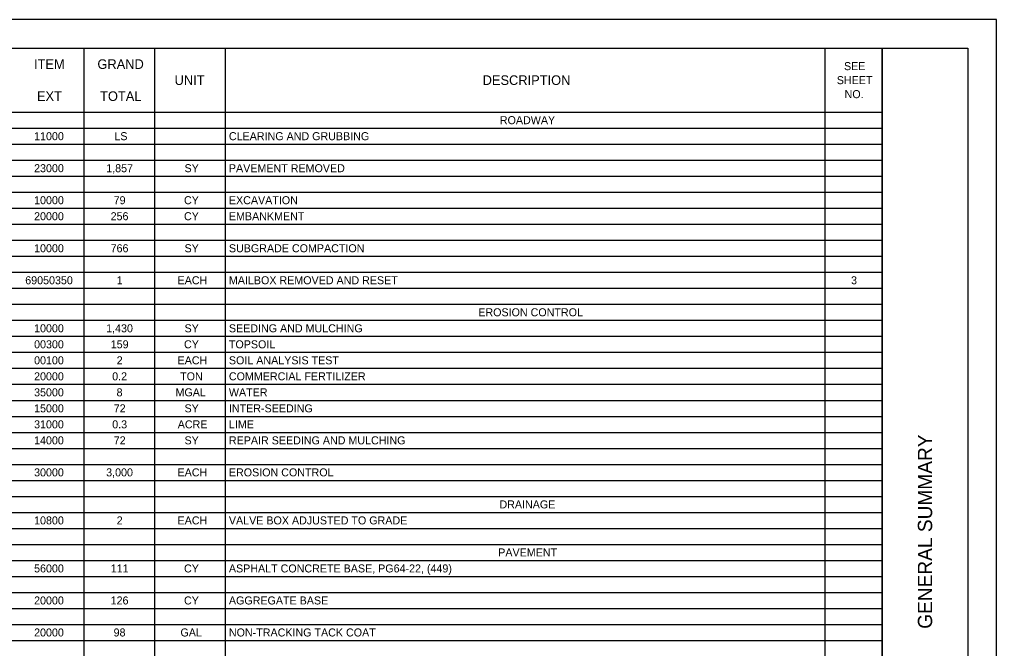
# Model space of a CAD drawing. Extents: x 0 to 34, y 0 to 22.
# Drawn here: x 16.91 to 34, y 11 to 22 of the extents above; entities that cross this region are included whole.
import ezdxf

# ---------------------------------------------------------------- set-up
doc = ezdxf.new("R2010")
doc.units = 0
for name, color, linetype in [('Default', 7, 'Continuous'), ('SH_Border', 7, 'Continuous'), ('SH_Cut_Line', 7, 'Continuous'), ('SH_Data', 7, 'Continuous')]:
    doc.layers.add(name, color=color, linetype=linetype)

msp = doc.modelspace()

# ---------------------------------------------------------------- linework, layer by layer
at = {"layer": 'Default'}
for p, q in [((1.5, 21.5), (32.002, 21.5)), ((18.036, 21.5), (18.036, 0.501)), ((19.271, 21.5), (19.271, 0.501)), ((20.506, 21.5), (20.506, 0.501)), ((30.998, 21.5), (30.998, 0.501)), ((32.002, 21.5), (32.002, 0.501)), ((1.5, 20.38), (32.002, 20.38)), ((1.5, 20.1), (32.002, 20.1)), ((1.5, 19.82), (32.002, 19.82)), ((1.5, 19.54), (32.002, 19.54)), ((1.5, 19.26), (32.002, 19.26)), ((1.5, 18.98), (32.002, 18.98)), ((1.5, 18.7), (32.002, 18.7)), ((1.5, 18.42), (32.002, 18.42)), ((1.5, 18.14), (32.002, 18.14)), ((1.5, 17.86), (32.002, 17.86)), ((1.5, 17.58), (32.002, 17.58)), ((1.5, 17.3), (32.002, 17.3)), ((1.5, 17.02), (32.002, 17.02)), ((1.5, 16.74), (32.002, 16.74)), ((1.5, 16.46), (32.002, 16.46)), ((1.5, 16.18), (32.002, 16.18)), ((1.5, 15.9), (32.002, 15.9)), ((1.5, 15.62), (32.002, 15.62)), ((1.5, 15.34), (32.002, 15.34)), ((1.5, 15.06), (32.002, 15.06)), ((1.5, 14.78), (32.002, 14.78)), ((1.5, 14.5), (32.002, 14.5)), ((1.5, 14.22), (32.002, 14.22)), ((1.5, 13.94), (32.002, 13.94)), ((1.5, 13.66), (32.002, 13.66)), ((1.5, 13.38), (32.002, 13.38)), ((1.5, 13.1), (32.002, 13.1)), ((1.5, 12.82), (32.002, 12.82)), ((1.5, 12.54), (32.002, 12.54)), ((1.5, 12.26), (32.002, 12.26)), ((1.5, 11.98), (32.002, 11.98)), ((1.5, 11.7), (32.002, 11.7)), ((1.5, 11.42), (32.002, 11.42)), ((1.5, 11.14), (32.002, 11.14))]:
    msp.add_line(p, q, dxfattribs=at)
at = {"layer": 'SH_Border'}
msp.add_line((32, 0.5), (32, 21.5), dxfattribs=at)
msp.add_lwpolyline([(1.5, 21.5), (33.5, 21.5), (33.5, 0.5), (1.5, 0.5)], close=True, dxfattribs=at)
at = {"layer": 'SH_Cut_Line'}
msp.add_lwpolyline([(0, 0), (34, 0), (34, 22), (0, 22)], close=True, dxfattribs=at)

# ---------------------------------------------------------------- texts
at = {"layer": 'Default'}
for s, height, p in [('ITEM', 0.168, (17.163, 21.136)), ('GRAND', 0.168, (18.272, 21.136)), ('SEE ', 0.14, (31.333, 21.115)), ('UNIT', 0.168, (19.622, 20.856)), ('DESCRIPTION', 0.168, (25.011, 20.856)), ('SHEET ', 0.14, (31.207, 20.87)), ('EXT', 0.168, (17.214, 20.576)), ('TOTAL', 0.168, (18.319, 20.576)), ('NO.', 0.14, (31.343, 20.625)), ('ROADWAY', 0.14, (25.312, 20.17)), ('11000', 0.14, (17.164, 19.89)), ('LS', 0.14, (18.568, 19.89)), ('CLEARING AND GRUBBING', 0.14, (20.572, 19.89)), ('23000', 0.14, (17.164, 19.33)), ('1,857', 0.14, (18.426, 19.33)), ('SY', 0.14, (19.796, 19.33)), ('PAVEMENT REMOVED', 0.14, (20.572, 19.33)), ('10000', 0.14, (17.164, 18.77)), ('79', 0.14, (18.556, 18.77)), ('CY', 0.14, (19.787, 18.77)), ('EXCAVATION', 0.14, (20.572, 18.77)), ('20000', 0.14, (17.164, 18.49)), ('256', 0.14, (18.503, 18.49)), ('CY', 0.14, (19.787, 18.49)), ('EMBANKMENT', 0.14, (20.572, 18.49)), ('10000', 0.14, (17.164, 17.93)), ('766', 0.14, (18.503, 17.93)), ('SY', 0.14, (19.796, 17.93)), ('SUBGRADE COMPACTION', 0.14, (20.572, 17.93)), ('69050350', 0.14, (17.009, 17.37)), ('1', 0.14, (18.609, 17.37)), ('EACH', 0.14, (19.674, 17.37)), ('MAILBOX REMOVED AND RESET', 0.14, (20.572, 17.37)), ('3', 0.14, (31.456, 17.37)), ('EROSION CONTROL', 0.14, (24.935, 16.81)), ('10000', 0.14, (17.164, 16.53)), ('1,430', 0.14, (18.425, 16.53)), ('SY', 0.14, (19.796, 16.53)), ('SEEDING AND MULCHING', 0.14, (20.572, 16.53)), ('00300', 0.14, (17.164, 16.25)), ('159', 0.14, (18.505, 16.25)), ('CY', 0.14, (19.787, 16.25)), ('TOPSOIL', 0.14, (20.572, 16.25)), ('00100', 0.14, (17.164, 15.97)), ('2', 0.14, (18.609, 15.97)), ('EACH', 0.14, (19.674, 15.97)), ('SOIL ANALYSIS TEST', 0.14, (20.572, 15.97)), ('20000', 0.14, (17.164, 15.69)), ('0.2', 0.14, (18.53, 15.69)), ('TON', 0.14, (19.719, 15.69)), ('COMMERCIAL FERTILIZER', 0.14, (20.572, 15.69)), ('35000', 0.14, (17.164, 15.41)), ('8', 0.14, (18.607, 15.41)), ('MGAL', 0.14, (19.638, 15.41)), ('WATER', 0.14, (20.572, 15.41)), ('15000', 0.14, (17.164, 15.13)), ('72', 0.14, (18.557, 15.13)), ('SY', 0.14, (19.796, 15.13)), ('INTER-SEEDING', 0.14, (20.572, 15.13)), ('31000', 0.14, (17.164, 14.85)), ('0.3', 0.14, (18.531, 14.85)), ('ACRE', 0.14, (19.677, 14.85)), ('LIME', 0.14, (20.572, 14.85)), ('14000', 0.14, (17.164, 14.57)), ('72', 0.14, (18.557, 14.57)), ('SY', 0.14, (19.796, 14.57)), ('REPAIR SEEDING AND MULCHING', 0.14, (20.572, 14.57)), ('30000', 0.14, (17.164, 14.01)), ('3,000', 0.14, (18.425, 14.01)), ('EACH', 0.14, (19.674, 14.01)), ('EROSION CONTROL', 0.14, (20.572, 14.01)), ('DRAINAGE', 0.14, (25.305, 13.45)), ('10800', 0.14, (17.164, 13.17)), ('2', 0.14, (18.609, 13.17)), ('EACH', 0.14, (19.674, 13.17)), ('VALVE BOX ADJUSTED TO GRADE', 0.14, (20.572, 13.17)), ('PAVEMENT', 0.14, (25.284, 12.61)), ('ASPHALT CONCRETE BASE, PG64-22, (449)', 0.14, (20.572, 12.33)), ('56000', 0.14, (17.164, 12.33)), ('111', 0.14, (18.505, 12.33)), ('CY', 0.14, (19.787, 12.33)), ('20000', 0.14, (17.164, 11.77)), ('126', 0.14, (18.503, 11.77)), ('CY', 0.14, (19.787, 11.77)), ('AGGREGATE BASE', 0.14, (20.572, 11.77)), ('20000', 0.14, (17.164, 11.21)), ('98', 0.14, (18.555, 11.21)), ('GAL', 0.14, (19.725, 11.21)), ('NON-TRACKING TACK COAT', 0.14, (20.572, 11.21))]:
    msp.add_text(s, height=height, dxfattribs=at).set_placement(p)
at = {"layer": 'SH_Data'}
msp.add_text('GENERAL SUMMARY', height=0.25, rotation=90, dxfattribs=at).set_placement((32.875, 11.344))

doc.saveas('drawing.dxf')
